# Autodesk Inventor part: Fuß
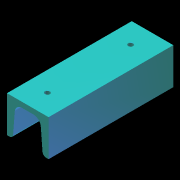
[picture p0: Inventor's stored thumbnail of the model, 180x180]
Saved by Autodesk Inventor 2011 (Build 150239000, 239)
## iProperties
Created: 2012-06
Part Number: Fuß
Document SubType Name: Modeling
Designer: M.Schulte
Density: 1 g/cm^3
Author: M.Schulte
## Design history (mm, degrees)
sketch "Skizze1"
  geometry: L1 (0, 35)-(40, 35); L2 (0, 0)-(0, 35); L3 (2.369, 0)-(0, 0); L4 (7.485, 23.558)-(5.858, 3.221); L5 (25.538, 30)-(14.462, 30); L6 (40, 0)-(37.631, 0); L7 (34.142, 3.221)-(32.515, 23.558); L8 (40, 35)-(40, 0); A1 r 7 centre (25.538, 23) between (32.515, 23.558) and (25.538, 30); A2 r 7 centre (14.462, 23) between (14.462, 30) and (7.485, 23.558); A3 r 3.5 centre (2.369, 3.5) between (2.369, 0) and (5.858, 3.221); A4 r 3.5 centre (37.631, 3.5) between (34.142, 3.221) and (37.631, 0); 1 further point
  constraints: 16 end point, 8 point on circle, 4 centre point
extrude "Extrusion1" new body sketch "Skizze1" distance "d0" = 120; taper "d1" = 0 deg
sketch "Skizze2"
  geometry: 3 further points
  constraints: 1 vertical alignment
  dimensions: "d2" = 80 distance of point (19, -20) point (19, -100); "d3" = 20 vertical distance of point (0, 0) point (19, -20); "d4" = 19 horizontal distance of point (0, 0) point (19, -20)
hole "Hole1" sketch "Skizze2" at (19, -100), (19, -20) diameter "d6" = 4.5; stored, may be unused: countersink angle "d10" = 90 deg, drill point angle "d12" = 118 deg; dims "d7" = 6, "d8" = 4, "d9" = 2, "d11" = 8
chamfer "Fase1" distance "d13" = 0.25; stored, may be unused: second distance "d14" = 2, angle "d15" = 45 deg
node "Volumenkörper1"
